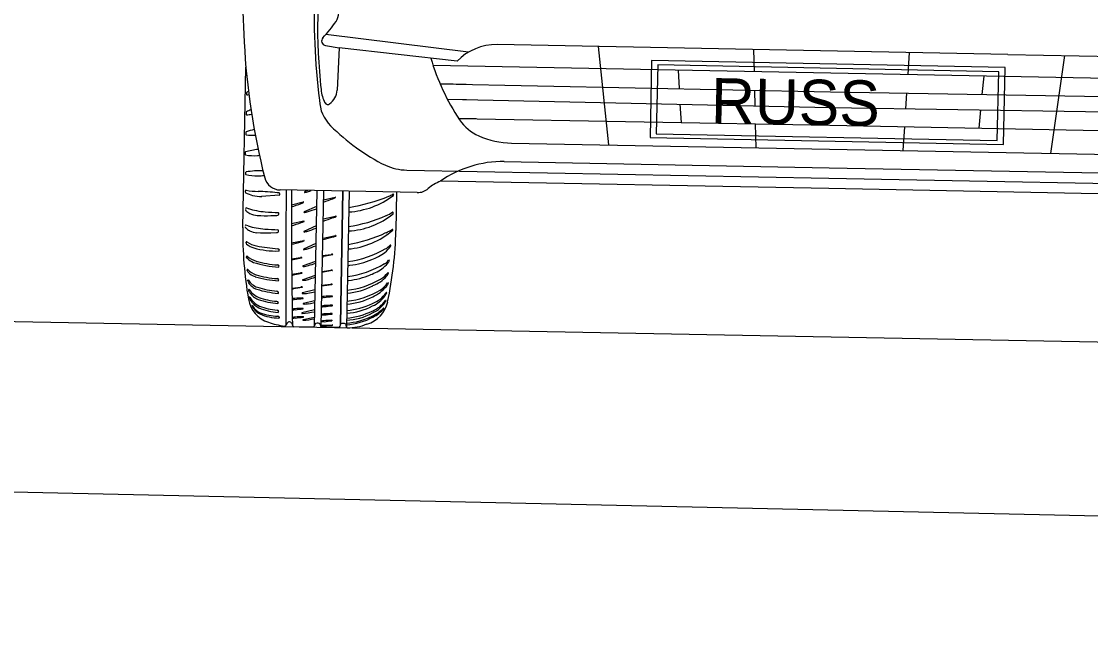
# Model space of a CAD drawing. Extents: x 10133 to 81668, y 4692 to 11018.
# Drawn here: x 29807.5 to 29939.6, y 6775.6 to 6850.6 of the extents above; entities that cross this region are included whole.
import ezdxf

# ---------------------------------------------------------------- set-up
doc = ezdxf.new("R2010")
doc.units = 0
for name, color, linetype in [('Cell', 7, 'Continuous'), ('Level 7', 7, 'Continuous'), ('PavementRemovalStage1', 7, 'Continuous'), ('SheetBorder', 7, 'Continuous')]:
    doc.layers.add(name, color=color, linetype=linetype)

msp = doc.modelspace()

# ---------------------------------------------------------------- linework, layer by layer
at = {"layer": 'Cell'}
for p, q in [((29862.7, 6846.8), (29845.1, 6848.99)), ((29845.05, 6847.62), (29846.72, 6847.34)), ((29929.33, 6846.53), (29866.23, 6847.73)), ((29878.73, 6847.49), (29879.99, 6835.35)), ((29897.9, 6847.13), (29897.98, 6844.39)), ((29917.15, 6846.76), (29916.98, 6844.03)), ((29929.33, 6846.53), (29948.83, 6846.16)), ((29936.33, 6846.4), (29934.61, 6834.31)), ((29834.83, 6825.13), (29835.2, 6844.95)), ((29888.6, 6844.56), (29888.73, 6842.3)), ((29926.35, 6843.85), (29926.14, 6841.59)), ((29862.4, 6842.83), (29859.19, 6842.89)), ((29835.29, 6841.77), (29835.29, 6841.58)), ((29835.34, 6841.53), (29835.34, 6841.53)), ((29898.03, 6842.1), (29898.08, 6840.17)), ((29916.83, 6841.75), (29916.71, 6839.81)), ((29862.47, 6840.92), (29860.1, 6840.97)), ((29888.83, 6840.37), (29888.96, 6838.12)), ((29835.24, 6839.37), (29835.24, 6839.13)), ((29863.67, 6838.58), (29861.49, 6838.63)), ((29925.96, 6839.67), (29925.75, 6837.42)), ((29898.14, 6837.95), (29898.22, 6835)), ((29916.57, 6837.6), (29916.38, 6834.66)), ((29835.2, 6836.91), (29835.2, 6836.67)), ((29835.13, 6834.42), (29835.12, 6834.18)), ((29835.16, 6831.96), (29835.16, 6831.77)), ((29907.21, 6829.95), (29859.24, 6830.86)), ((29835.14, 6829.51), (29835.14, 6829.69)), ((29839.35, 6829.24), (29839.34, 6829.18)), ((29839.36, 6829.37), (29839.35, 6829.24)), ((29856.38, 6829.47), (29839.44, 6829.79)), ((29842.81, 6829.73), (29842.46, 6829.57)), ((29843.96, 6829.7), (29843.64, 6812.97)), ((29844.79, 6829.69), (29844.48, 6812.95)), ((29847.95, 6829.63), (29847.63, 6812.85)), ((29853.83, 6829.52), (29853.74, 6824.78)), ((29955.18, 6829.04), (29907.21, 6829.95)), ((29839.32, 6829.16), (29837.15, 6829)), ((29840.84, 6827.97), (29842.29, 6828.32)), ((29844.78, 6828.57), (29846.23, 6828.92)), ((29853.42, 6829.1), (29853.42, 6829.1)), ((29853.46, 6829.19), (29853.46, 6829.19)), ((29835.53, 6827.48), (29835.24, 6827.58)), ((29838.3, 6826.62), (29839.03, 6826.65)), ((29839.2, 6827.01), (29839.2, 6827.01)), ((29839.24, 6826.71), (29839.24, 6826.71)), ((29843.93, 6827.76), (29842.41, 6827.09)), ((29853.38, 6826.84), (29853.38, 6826.84)), ((29853.41, 6826.94), (29853.41, 6826.94)), ((29835.49, 6825.36), (29835.2, 6825.45)), ((29840.83, 6825.64), (29842.35, 6825.96)), ((29843.88, 6825.35), (29842.36, 6824.68)), ((29844.77, 6826.24), (29846.29, 6826.56)), ((29838.26, 6824.5), (29838.99, 6824.52)), ((29839.16, 6824.88), (29839.16, 6824.88)), ((29839.2, 6824.58), (29839.2, 6824.58)), ((29844.77, 6823.85), (29846.29, 6824.17)), ((29853.26, 6824.91), (29853.26, 6824.91)), ((29853.34, 6824.82), (29853.34, 6824.82)), ((29853.37, 6824.91), (29853.37, 6824.91)), ((29835.22, 6823.26), (29835.22, 6823.34)), ((29840.83, 6823.25), (29842.35, 6823.57)), ((29843.84, 6823.17), (29842.32, 6822.5)), ((29835.28, 6821.47), (29835.28, 6821.55)), ((29840.84, 6821.29), (29841.94, 6821.46)), ((29842.09, 6821.39), (29841.03, 6821.18)), ((29844.64, 6821.68), (29845.75, 6821.84)), ((29845.9, 6821.77), (29844.84, 6821.56)), ((29843.8, 6820.97), (29842.27, 6820.43)), ((29835.36, 6819.85), (29835.35, 6819.93)), ((29840.85, 6819.38), (29841.96, 6819.55)), ((29842.11, 6819.48), (29841.05, 6819.27)), ((29843.76, 6819.25), (29842.23, 6818.71)), ((29844.6, 6819.73), (29845.71, 6819.89)), ((29852.58, 6819.14), (29852.58, 6819.14)), ((29835.43, 6818.53), (29835.42, 6818.61)), ((29835.52, 6817.44), (29835.52, 6817.44)), ((29840.87, 6817.68), (29842, 6817.81)), ((29842.15, 6817.74), (29841.07, 6817.57)), ((29843.73, 6817.45), (29842.18, 6817.09)), ((29844.57, 6818.03), (29845.69, 6818.16)), ((29852.57, 6817.89), (29852.57, 6817.89)), ((29840.89, 6816.3), (29840.89, 6816.3)), ((29843.7, 6816.12), (29842.31, 6815.79)), ((29847.71, 6817.05), (29847.71, 6817.05)), ((29852.36, 6816.68), (29852.36, 6816.68)), ((29840.92, 6815.03), (29840.92, 6815.03)), ((29843.68, 6814.98), (29842.13, 6814.62)), ((29843.68, 6814.77), (29843.68, 6814.77)), ((29844.52, 6815.43), (29844.52, 6815.43)), ((29847.68, 6815.69), (29847.68, 6815.69)), ((29840.94, 6814.04), (29840.94, 6814.04)), ((29843.67, 6814.06), (29842.26, 6813.77)), ((29844.49, 6813.61), (29844.49, 6813.61)), ((29844.51, 6814.43), (29844.51, 6814.43)), ((29847.65, 6813.71), (29847.65, 6813.71)), ((29847.66, 6814.59), (29847.66, 6814.59)), ((29840.31, 6813.36), (29840.14, 6813.07)), ((29843.55, 6812.86), (29841.13, 6812.9)), ((29843.74, 6813.23), (29843.74, 6813.23)), ((29844.39, 6813.22), (29844.39, 6813.22)), ((29844.48, 6813.1), (29845.88, 6813.14)), ((29846.67, 6812.8), (29844.57, 6812.84)), ((29846.89, 6813.22), (29846.89, 6813.22)), ((29847.63, 6812.85), (29847.63, 6812.85)), ((29847.64, 6813.15), (29847.64, 6813.15))]:
    msp.add_line(p, q, dxfattribs=at)
for points in [[(29861.29, 6845.69), (29846.72, 6847.34), (29846.47, 6842.11)], [(29956.62, 6843.27), (29907.48, 6844.21), (29858.33, 6845.14)], [(29859.18, 6842.91), (29907.43, 6841.91), (29955.69, 6841.08)], [(29860.08, 6841.01), (29907.4, 6839.96), (29954.72, 6839.21)], [(29861.49, 6838.62), (29907.36, 6837.78), (29953.22, 6836.88)], [(29868.03, 6835.58), (29907.3, 6834.83), (29946.57, 6834.09)], [(29867.13, 6833.29), (29907.26, 6832.53), (29947.38, 6831.77)], [(29855.08, 6832.24), (29907.23, 6831.25), (29959.38, 6830.26)], [(29847.18, 6829.64), (29846.89, 6813.22), (29847.2, 6829.64)], [(29845.86, 6819.83), (29844.6, 6819.58), (29844.6, 6819.58)], [(29845.84, 6818.09), (29844.57, 6817.9), (29844.57, 6817.9)], [(29835.61, 6816.52), (29835.61, 6816.52), (29835.61, 6816.52)], [(29852.51, 6816.11), (29852.51, 6816.11), (29852.51, 6816.11)], [(29835.93, 6815.51), (29835.93, 6815.51), (29835.93, 6815.51)], [(29852.25, 6815.16), (29852.25, 6815.16), (29852.25, 6815.16)], [(29844.13, 6813.34), (29844.07, 6813.34), (29844.01, 6813.34)]]:
    msp.add_lwpolyline(points, dxfattribs=at)
for centre, radius, start, end in [((30080.39, 6860.14), 245.7, 179.3199, 182.823), ((29928.26, 6851.29), 84.62, 177.5868, 187.0739), ((30014.61, 6848.65), 170.55, 178.16, 179.6346), ((29832.44, 6860.09), 16.83, 316.7788, 325.6715), ((29844.67, 6851.74), 2.02, 325.6715, 356.7814), ((29894.6, 6849.42), 50.54, 179.6346, 183.0948), ((29919.12, 6852.23), 84.23, 182.8523, 194.386), ((29845.12, 6848.18), 0.561, 136.7788, 262.8692), ((29866.11, 6841.01), 6.72, 88.9136, 135.867), ((29935.09, 6851.6), 91.09, 183.0948, 185.9409), ((29884.47, 6853.78), 27.53, 196.2813, 213.8519), ((29835.35, 6841.78), 0.0661, 116.4403, 183.6111), ((29835.35, 6841.58), 0.057, 179.8862, 261.0398), ((29838.72, 6835.43), 7.25, 116.2011, 117.9409), ((29829.04, 6877.32), 36.34, 279.9779, 280.3442), ((29849.02, 6842.65), 4.56, 185.9409, 207.3978), ((29844.26, 6842.22), 2.21, 305.1657, 357.2859), ((29849.01, 6841.07), 4.73, 182.3888, 224.968), ((29845.32, 6840.73), 0.385, 207.3978, 305.1657), ((29835.29, 6839.38), 0.0478, 110.0675, 199.2421), ((29835.3, 6839.13), 0.057, 179.8862, 261.0398), ((29838.53, 6832.99), 7.22, 111.9698, 116.8289), ((29786.98, 7228.38), 392.3, 277.0733, 277.1645), ((29837.51, 6830.7), 6.67, 101.0822, 110.0675), ((29863.99, 6856.02), 25.9, 224.968, 243.5202), ((29866.18, 6841.51), 5.5, 213.8519, 246.2435), ((29835.24, 6836.92), 0.0478, 110.0675, 199.2421), ((29835.25, 6836.67), 0.057, 179.8862, 261.0398), ((29836.06, 6841.77), 5.23, 261.0398, 273.3092), ((29868.23, 6846.15), 10.58, 246.2435, 268.9136), ((29837.2, 6828.13), 6.67, 94.1299, 107.7782), ((29835.18, 6834.18), 0.057, 177.5969, 258.7505), ((29835.17, 6834.44), 0.0478, 107.7782, 196.9528), ((29836.18, 6839.25), 5.23, 258.7505, 275.058), ((29834.38, 6859.65), 25.7, 275.058, 275.5644), ((29866.88, 6820.06), 13.23, 88.9136, 125.2898), ((29835.22, 6831.95), 0.0628, 93.608, 174.6476), ((29837.09, 6820.04), 12.12, 88.9379, 98.8727), ((29855.21, 6838.9), 6.66, 245.4212, 268.9136), ((29835.22, 6831.77), 0.057, 173.8471, 255.0007), ((29836.56, 6836.76), 5.23, 255.0007, 271.3082), ((29836.09, 6857.23), 25.7, 271.3082, 273.0657), ((29839.48, 6831.8), 2.01, 194.386, 268.9136), ((29860.97, 6826.26), 4.92, 110.6831, 131.1511), ((29835.23, 6829.67), 0.0931, 77.0029, 170.8779), ((29835.22, 6829.51), 0.0805, 179.4676, 231.0111), ((29837.11, 6833.06), 4.1, 241.7341, 254.7078), ((29837.09, 6840.45), 10.85, 260.2232, 268.0104), ((29835.45, 6793.2), 36.43, 84.3003, 88.0104), ((29837.82, 6816.93), 12.58, 83.1752, 84.3003), ((29839.31, 6829.38), 0.0456, 349.4711, 83.1752), ((30924.46, 6818.95), 1084.33, 179.4279, 180.31037), ((30542.43, 6826.36), 701.6, 179.72197, 181.08208), ((29842.47, 6829.53), 0.0401, 113.816, 280.3188), ((29841.85, 6832.93), 3.5, 280.3188, 287.9522), ((29825.69, 6882.8), 55.92, 287.9522, 288.3201), ((29846.43, 6844.83), 15.28, 275.6857, 275.7508), ((29852.29, 6830.78), 1.84, 288.6459, 305.4405), ((29853.39, 6829.23), 0.0595, 23.5343, 125.4405), ((29853.27, 6829.17), 0.193, 5.6775, 23.5343), ((29856.41, 6831.48), 2.01, 268.9136, 311.1511), ((29836.91, 6832.33), 3.34, 254.7078, 274.1828), ((29839.32, 6829.18), 0.0264, 278.9059, 358.1), ((29822.79, 6880.62), 55.92, 288.8277, 290.1121), ((29841.45, 6829.81), 1.79, 288.475, 299.1398), ((29842.3, 6828.28), 0.0401, 297.7454, 104.2482), ((29826.73, 6881.22), 55.92, 288.8277, 290.1121), ((29845.39, 6830.41), 1.79, 288.475, 299.1398), ((29846.24, 6828.88), 0.0401, 297.7454, 104.2482), ((29847.24, 6837.39), 10.34, 273.6611, 306.6971), ((29844.24, 6850.43), 23.08, 279.1463, 291.9748), ((29853.31, 6829.2), 0.148, 315.1898, 356.1698), ((29835.23, 6827.48), 0.0975, 87.4743, 159.2711), ((29835.38, 6827.4), 0.234, 186.9372, 225.573), ((29836.5, 6828.54), 1.83, 225.573, 244.0713), ((29838.01, 6835.21), 8.11, 252.2322, 259.4863), ((29836.79, 6829.14), 2.5, 244.0713, 265.9574), ((29838.54, 6838.08), 11.03, 259.4863, 265.0641), ((29837.7, 6842.02), 15.41, 265.9574, 272.2484), ((29839.6, 6850.3), 23.3, 265.0641, 269.0302), ((29838.95, 6827.38), 0.736, 276.3907, 293.2579), ((29839.07, 6826.84), 0.213, 322.0172, 52.3372), ((29842.42, 6827.05), 0.0401, 113.816, 280.3188), ((29841.81, 6830.45), 3.5, 280.3188, 287.9522), ((29825.65, 6880.32), 55.92, 287.9522, 289.0727), ((29847.42, 6834.14), 9.42, 272.6776, 309.2611), ((29845.36, 6842.75), 17.65, 278.1541, 294.042), ((29851.46, 6829.62), 3.18, 290.1273, 305.4776), ((29853.34, 6826.98), 0.0595, 17.9785, 125.4776), ((29853.31, 6826.92), 0.0984, 309.8854, 11.3041), ((29853.07, 6826.89), 0.345, 8.0523, 17.9785), ((29835.19, 6825.36), 0.0975, 87.4743, 159.2711), ((29837.97, 6833.08), 8.11, 252.2322, 259.4863), ((29822.8, 6878.28), 55.92, 288.8083, 290.1121), ((29841.54, 6827.92), 2.2, 282.628, 292.2443), ((29842.36, 6825.92), 0.0401, 297.7454, 104.2482), ((29826.74, 6878.88), 55.92, 288.8083, 290.1121), ((29845.48, 6828.52), 2.2, 282.628, 292.2443), ((29846.3, 6826.52), 0.0401, 297.7454, 104.2482), ((29882.65, 6824.43), 47.83, 179.1544, 189.7757), ((29835.34, 6825.27), 0.234, 186.9372, 225.573), ((29836.46, 6826.42), 1.83, 225.573, 244.0713), ((29836.75, 6827.01), 2.5, 244.0713, 265.9574), ((29838.5, 6835.95), 11.03, 259.4863, 265.0641), ((29837.66, 6839.89), 15.41, 265.9574, 272.2484), ((29839.56, 6848.18), 23.3, 265.0641, 269.0302), ((29838.91, 6825.26), 0.736, 276.3907, 293.2579), ((29839.03, 6824.71), 0.213, 322.0172, 52.3372), ((29842.38, 6824.64), 0.0401, 113.816, 280.3188), ((29841.76, 6828.04), 3.5, 280.3188, 287.9522), ((29825.6, 6877.91), 55.92, 287.9522, 289.0727), ((29839.96, 6845.08), 21.93, 282.6646, 285.9005), ((29845.49, 6826.14), 2.2, 282.628, 292.2443), ((29846.3, 6824.13), 0.0401, 297.7454, 104.2482), ((29847.03, 6832.13), 9.66, 274.6666, 310.7862), ((29844.9, 6840.7), 17.88, 279.395, 295.1779), ((29849.21, 6831.69), 7.9, 294.7147, 300.8901), ((29805.92, 6825.88), 47.83, 348.0515, 358.6727), ((29853.32, 6824.83), 0.0982, 58.9628, 124.5453), ((29853.27, 6824.89), 0.0984, 309.8854, 11.3041), ((29835.28, 6823.34), 0.0595, 54.8931, 181.7148), ((29835.42, 6823.26), 0.195, 182.4181, 228.841), ((29836.82, 6824.86), 2.32, 228.841, 254.0969), ((29837.06, 6825.87), 3.04, 234.8931, 259.7489), ((29841.52, 6850.49), 28.06, 259.7489, 265.1378), ((29836.02, 6844.48), 21.93, 282.6646, 285.9005), ((29841.55, 6825.54), 2.2, 282.628, 292.2443), ((29842.36, 6823.53), 0.0401, 297.7454, 104.2482), ((29825.56, 6875.73), 55.92, 287.9522, 289.0727), ((29850.17, 6824.84), 3.53, 308.6885, 324.9841), ((29851.81, 6823.95), 1.55, 297.0215, 321.3976), ((29853.06, 6822.95), 0.0462, 359.4486, 141.3976), ((29852.86, 6822.96), 0.245, 324.9841, 359.4486), ((29835.34, 6821.55), 0.0595, 54.8931, 181.7148), ((29835.64, 6821.58), 0.37, 196.1821, 226.2966), ((29837.24, 6823.73), 2.83, 228.7839, 254.5814), ((29838.92, 6832.25), 10, 254.0969, 272.0169), ((29839.12, 6822.31), 0.225, 15.8587, 85.1378), ((29839.24, 6822.34), 0.0933, 286.9678, 15.8587), ((29842.18, 6817.96), 3.51, 91.5266, 93.8043), ((29842.09, 6821.42), 0.0377, 281.7975, 93.5919), ((29842.34, 6822.46), 0.0401, 113.816, 280.3188), ((29841.72, 6825.86), 3.5, 280.3188, 287.9522), ((29844.59, 6822.79), 1.25, 272.5245, 281.4446), ((29845.98, 6818.34), 3.51, 91.5266, 93.8043), ((29845.89, 6821.81), 0.0377, 281.7975, 93.5919), ((29846.3, 6832.98), 12.12, 277.0187, 300.8269), ((29849.19, 6826.06), 5.09, 287.9809, 308.6885), ((29835.41, 6819.93), 0.0595, 54.8931, 181.7148), ((29837.71, 6824.27), 3.76, 231.9359, 245.5453), ((29840.21, 6833.88), 13.65, 252.6896, 265.9049), ((29839.95, 6832.91), 12.4, 253.7821, 266.0727), ((29839.08, 6820.32), 0.225, 15.8587, 85.1378), ((29839.21, 6820.35), 0.0933, 286.9678, 15.8587), ((29840.78, 6822.41), 1.25, 272.5245, 281.4446), ((29842.28, 6820.39), 0.0401, 113.816, 280.3188), ((29842.25, 6822.58), 2.23, 270.9592, 288.1623), ((29825.52, 6873.6), 55.92, 288.1613, 289.0727), ((29846.14, 6831.02), 12.04, 277.6657, 300.9369), ((29846.47, 6836.58), 16.17, 274.6243, 275.6472), ((29846.72, 6830.9), 10.5, 277.3575, 292.6696), ((29849.01, 6824.18), 5.09, 287.9809, 308.6885), ((29849.99, 6822.96), 3.53, 308.6885, 324.9841), ((29851.63, 6822.07), 1.55, 297.0215, 321.3976), ((29852.88, 6821.07), 0.0462, 359.4486, 141.3976), ((29852.68, 6821.08), 0.245, 324.9841, 359.4486), ((29835.71, 6819.96), 0.37, 196.1821, 226.2966), ((29837.33, 6821.75), 2.58, 223.138, 250.1147), ((29837.07, 6821.13), 2.16, 221.8152, 251.0321), ((29840.18, 6832.19), 13.65, 253.7822, 265.9049), ((29839.92, 6831.22), 12.4, 253.7821, 266.0727), ((29839.05, 6818.63), 0.225, 15.8587, 85.1378), ((29839.17, 6818.67), 0.0933, 286.9678, 15.8587), ((29840.8, 6820.5), 1.25, 272.5245, 281.4446), ((29842.19, 6816.05), 3.51, 91.5266, 93.8043), ((29842.1, 6819.52), 0.0377, 281.7975, 93.5919), ((29842.25, 6818.67), 0.0401, 113.816, 280.3188), ((29842.22, 6820.87), 2.23, 270.9592, 288.1623), ((29825.49, 6871.88), 55.92, 288.1613, 289.0727), ((29845.94, 6816.4), 3.51, 91.5266, 93.8043), ((29845.85, 6819.86), 0.0377, 281.7975, 93.5919), ((29846.43, 6828.1), 10.77, 276.8835, 300.116), ((29846.54, 6829.02), 10.5, 277.3575, 292.6696), ((29849.41, 6821.93), 4.22, 290.701, 318.765), ((29850.53, 6821.18), 2.73, 298.364, 324.038), ((29851.28, 6820.2), 1.68, 321.1397, 337.382), ((29852.78, 6819.55), 0.0462, 359.4486, 141.3976), ((29835.48, 6818.61), 0.0595, 54.8931, 181.7148), ((29836.07, 6818.76), 0.684, 199.6517, 217.1824), ((29837.45, 6819.94), 2.32, 213.5395, 248.945), ((29837.25, 6819.48), 2.07, 213.2633, 249.9881), ((29835.58, 6817.44), 0.0595, 54.8931, 181.7148), ((29836.18, 6817.58), 0.679, 192.3701, 224.5585), ((29837.89, 6819.01), 2.73, 213.808, 246.4), ((29840.47, 6830.72), 13.76, 253.4256, 264.5853), ((29840.21, 6829.75), 12.5, 253.3109, 264.6389), ((29840.82, 6818.8), 1.25, 272.5245, 281.4446), ((29842.23, 6814.31), 3.51, 91.5266, 93.8043), ((29842.14, 6817.78), 0.0377, 281.7975, 93.5919), ((29845.93, 6814.66), 3.51, 91.5266, 93.8043), ((29845.84, 6818.13), 0.0377, 281.7975, 93.5919), ((29846.4, 6826.74), 10.77, 276.8835, 300.116), ((29847.02, 6825.38), 8.36, 274.7088, 297.6326), ((29846.29, 6834.7), 16.17, 275.1412, 275.6472), ((29849.07, 6820.76), 4.52, 293.4545, 320.579), ((29850.13, 6820.04), 3.1, 302.5319, 326.6063), ((29851.26, 6818.94), 1.68, 321.1397, 337.382), ((29852.76, 6818.3), 0.0462, 359.4486, 141.3976), ((29839.09, 6816.92), 3.63, 189.7757, 252.172), ((29835.66, 6816.51), 0.0463, 30.7344, 172.081), ((29837.72, 6817.3), 2.25, 200.4583, 246.1186), ((29837.5, 6818.25), 2.13, 212.4212, 248.6055), ((29837.96, 6817.84), 2.61, 209.9521, 245.58), ((29840.34, 6827.53), 11.83, 252.1982, 264.2349), ((29840.07, 6826.59), 10.6, 251.9613, 264.2609), ((29839, 6815.81), 0.225, 15.8587, 85.1378), ((29839.02, 6817.08), 0.225, 15.8587, 85.1378), ((29839.15, 6817.11), 0.0933, 286.9678, 15.8587), ((29841.24, 6815.7), 0.694, 89.8845, 119.9013), ((29841.46, 6815.19), 1.11, 100.7677, 120.7559), ((29842.64, 6799.91), 16.55, 91.3883, 94.8567), ((29832.88, 6892.48), 76.66, 276.2718, 277.014), ((29842.19, 6817.05), 0.0401, 107.5057, 274.0086), ((29842.4, 6819.23), 2.23, 264.6489, 281.852), ((29842.24, 6816.42), 0.0287, 273.7791, 88.092), ((29831.37, 6871.77), 55.92, 281.851, 282.7624), ((29845.1, 6815.44), 1.11, 100.7677, 120.03), ((29845.08, 6814.38), 2.27, 95.1032, 103.5146), ((29846.28, 6800.15), 16.55, 91.3883, 94.8567), ((29836.51, 6892.73), 76.66, 276.2718, 277.014), ((29845.87, 6816.67), 0.0287, 273.7791, 88.092), ((29847, 6824.02), 8.36, 274.7088, 297.6326), ((29849.3, 6818.44), 3.91, 292.9719, 323.9876), ((29849.43, 6819.26), 3.77, 292.0253, 325.1505), ((29849.41, 6817.88), 3.57, 293.5596, 330.3414), ((29849.38, 6818.9), 3.72, 293.3099, 323.2363), ((29851.05, 6817.73), 1.68, 321.1397, 337.382), ((29852.48, 6816.12), 0.0345, 330.8951, 137.0783), ((29852.56, 6817.08), 0.0462, 359.4486, 141.3976), ((29835.96, 6815.51), 0.0301, 42.63, 187.305), ((29837.95, 6816.48), 2.24, 205.5437, 242.368), ((29837.99, 6816.76), 2.36, 211.4589, 244.0909), ((29839.75, 6822.42), 7.76, 247.6896, 265.8157), ((29839.66, 6822.58), 7.65, 248.6587, 265.452), ((29839.04, 6814.74), 0.225, 15.8587, 85.1378), ((29839.12, 6815.85), 0.0933, 286.9678, 15.8587), ((29839.16, 6814.77), 0.0933, 286.9678, 15.8587), ((29841.26, 6814.43), 0.694, 89.8845, 119.9013), ((29841.49, 6813.91), 1.11, 100.7677, 120.7559), ((29842.66, 6798.63), 16.55, 91.3883, 94.8567), ((29832.9, 6891.2), 76.66, 276.2718, 277.014), ((29840.89, 6828.27), 13.79, 275.195, 281.6515), ((29842.26, 6815.14), 0.0287, 273.7791, 88.092), ((29842.32, 6815.75), 0.0401, 107.5057, 274.0086), ((29842.53, 6817.94), 2.23, 264.6489, 281.852), ((29831.51, 6870.48), 55.92, 281.851, 282.5935), ((29844.99, 6814.17), 1.34, 95.2972, 110.5669), ((29844.99, 6814.42), 0.975, 95.8924, 118.4435), ((29846.27, 6799.02), 16.55, 91.3883, 94.8567), ((29836.51, 6891.59), 76.66, 276.2718, 277.014), ((29845.87, 6815.53), 0.0287, 273.7791, 88.092), ((29846.73, 6823.44), 9.52, 275.5598, 295.4709), ((29847.26, 6822.18), 7.6, 273.0486, 298.2117), ((29846.75, 6824.6), 9.73, 275.416, 294.8541), ((29849.17, 6816.73), 3.63, 285.6552, 348.0515), ((29848.86, 6818.44), 4.65, 294.5617, 315.8529), ((29849.31, 6817.5), 3.76, 295.1183, 321.6121), ((29852.22, 6815.18), 0.0345, 330.8951, 137.0783), ((29839.33, 6820.02), 6.04, 246.3941, 269.6441), ((29839.33, 6820.84), 6.64, 249.043, 268.4553), ((29841.29, 6822.79), 9.89, 250.4328, 262.293), ((29839.13, 6813.98), 0.225, 20.6155, 85.1378), ((29839.29, 6814.05), 0.0609, 272.7755, 15.824), ((29840.55, 6813.22), 0.277, 77.2611, 148.9158), ((29840.45, 6812.79), 0.718, 60.1153, 77.2611), ((29840.68, 6813.18), 0.257, 23.6291, 60.1153), ((29844.28, 6790.32), 23.96, 97.1721, 98.0136), ((29842.02, 6809.01), 5.01, 98.3226, 102.5145), ((29842.69, 6797.6), 16.55, 91.3883, 94.8567), ((29832.92, 6890.17), 76.66, 276.2718, 277.014), ((29842.14, 6814.58), 0.0401, 107.5057, 274.0086), ((29842.28, 6813.74), 0.0342, 115.7565, 263.8783), ((29841.43, 6825.44), 11.77, 274.1227, 280.9564), ((29842.28, 6814.12), 0.0287, 273.7791, 88.092), ((29845.23, 6807.92), 5.73, 93.9574, 97.4602), ((29845.58, 6803.59), 9.96, 94.1844, 96.296), ((29845.1, 6811.25), 3.11, 94.2904, 101.0846), ((29847.85, 6790.7), 23.96, 97.1721, 98.0136), ((29846.24, 6797.15), 16.55, 91.3883, 94.8567), ((29846.25, 6797.99), 16.55, 91.3883, 94.8567), ((29836.48, 6889.73), 76.66, 276.2718, 277.014), ((29836.49, 6890.56), 76.66, 276.2718, 277.014), ((29845.84, 6813.67), 0.0287, 273.7791, 88.092), ((29845.85, 6814.5), 0.0287, 273.7791, 88.092), ((29847.12, 6821.5), 8.16, 273.6547, 296.7496), ((29847.06, 6821.26), 8.13, 274.0614, 298.2016), ((29847.24, 6821.3), 7.6, 273.0486, 298.2117), ((29839.99, 6813.17), 0.179, 262.9278, 328.9158), ((29840.52, 6813.11), 0.434, 359.2668, 23.6291), ((29841.15, 6813.1), 0.198, 177.3341, 264.1641), ((29843.53, 6812.97), 0.116, 279.6121, 357.2038), ((29844.11, 6812.94), 0.462, 141.6465, 177.2038), ((29843.99, 6813.01), 0.334, 88.0571, 138.6482), ((29844.13, 6813.01), 0.334, 39.179, 89.7701), ((29844.02, 6812.94), 0.462, 0.6233, 36.1807), ((29818.26, 7291.15), 478.88, 273.138, 273.3059), ((29844.59, 6812.95), 0.116, 180.6233, 258.2151), ((29845.88, 6813.11), 0.0337, 270.2831, 93.1072), ((29846.65, 6813), 0.198, 273.6631, 349.1936), ((29841.1, 6814.09), 5.86, 348.8194, 351.4629), ((29847.22, 6812.75), 0.573, 55.1746, 124.4026), ((29846.82, 6812.86), 0.807, 358.9314, 26.5476), ((29847.73, 6812.88), 0.104, 199.5348, 269.0031), ((29847.82, 6818.84), 6.06, 269.1195, 292.5741)]:
    msp.add_arc(centre, radius, start, end, dxfattribs=at)
at = {"layer": 'Level 7'}
msp.add_line((30566.15, 6775.64), (29752.89, 6793.67), dxfattribs=at)
at = {"layer": 'PavementRemovalStage1'}
msp.add_line((29752.89, 6814.58), (30624.93, 6798.04), dxfattribs=at)
at = {"layer": 'SheetBorder'}
for points in [[(29928.99, 6844.9), (29885.32, 6845.76), (29885.13, 6836.26), (29928.8, 6835.4)], [(29928.21, 6844.39), (29886.09, 6845.22), (29885.91, 6836.71), (29928.03, 6835.88)]]:
    msp.add_lwpolyline(points, close=True, dxfattribs=at)

# ---------------------------------------------------------------- texts
msp.add_text('RUSS', height=5.612, rotation=359.0952, dxfattribs=at).set_placement((29892.63, 6838))

doc.saveas('drawing.dxf')
